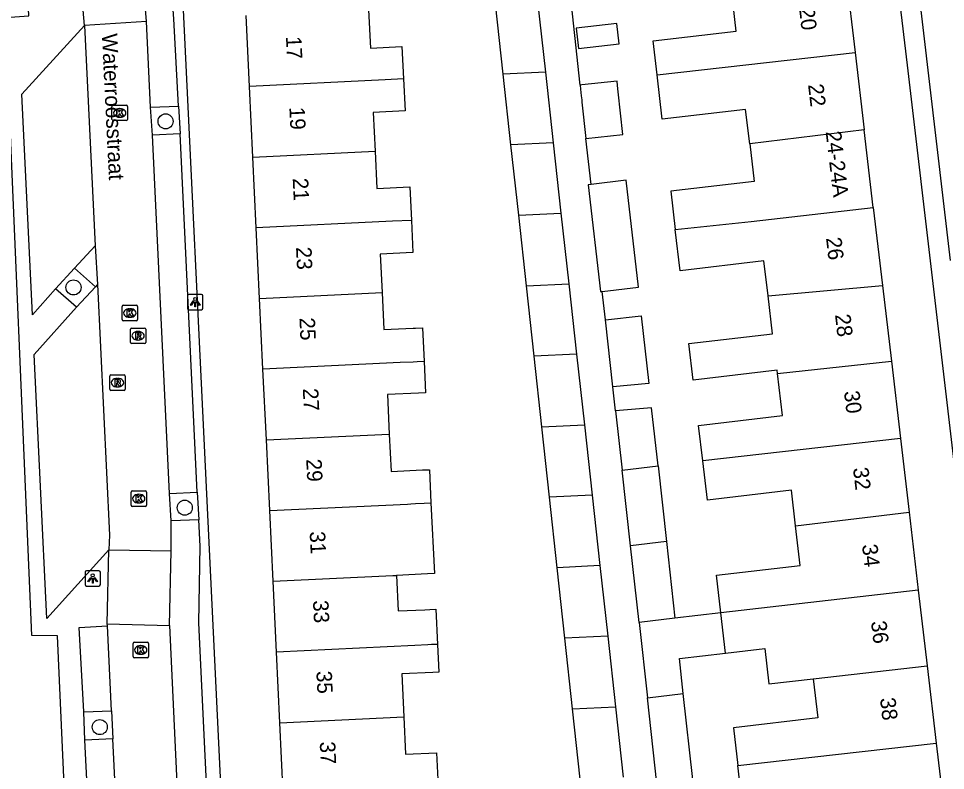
# Model space of a CAD drawing. Extents: x 162250 to 162654, y 380744 to 381605.
# Drawn here: x 162393.2 to 162453.3, y 381013.5 to 381062.2 of the extents above; entities that cross this region are included whole.
import ezdxf

# ---------------------------------------------------------------- set-up
doc = ezdxf.new("R2010")
doc.units = 0
for name, color, linetype in [('IMGEO_Boom', 7, 'Continuous'), ('IMGEO_Kolk', 7, 'Continuous'), ('IMGEO_Lichtpunt', 7, 'Continuous'), ('IMGEO_Openbare_ruimte_label', 7, 'Continuous'), ('IMGEO_Pand', 7, 'Continuous'), ('IMGEO_Pand_nummerreeks', 7, 'Continuous'), ('IMGEO_Parkeervlak_open', 7, 'Continuous'), ('IMGEO_Rijbaan_lokaal_open', 7, 'Continuous'), ('IMGEO_Rioolput', 7, 'Continuous'), ('IMGEO_Voetpad_open', 7, 'Continuous')]:
    doc.layers.add(name, color=color, linetype=linetype)

msp = doc.modelspace()

# ---------------------------------------------------------------- linework, layer by layer
at = {"layer": 'IMGEO_Boom'}
for centre in [(162402.768, 381055.57), (162396.792, 381044.803), (162404.011, 381030.518), (162398.497, 381016.292)]:
    msp.add_circle(centre, 0.489, dxfattribs=at)
at = {"layer": 'IMGEO_Kolk'}
for p, q in [((162399.291, 381055.69), (162399.291, 381056.542)), ((162399.366, 381056.616), (162400.218, 381056.616)), ((162399.779, 381056.396), (162399.804, 381056.396)), ((162400.292, 381056.542), (162400.292, 381055.69)), ((162399.802, 381055.836), (162399.777, 381055.836)), ((162400.218, 381055.616), (162399.366, 381055.616)), ((162399.948, 381042.717), (162399.948, 381043.569)), ((162400.023, 381043.643), (162400.875, 381043.643)), ((162400.436, 381043.423), (162400.461, 381043.423)), ((162400.949, 381043.569), (162400.949, 381042.717)), ((162400.875, 381042.643), (162400.023, 381042.643)), ((162400.459, 381042.863), (162400.434, 381042.863)), ((162400.529, 381030.678), (162400.529, 381031.53)), ((162400.604, 381031.604), (162401.456, 381031.604)), ((162401.017, 381031.384), (162401.042, 381031.384)), ((162401.53, 381031.53), (162401.53, 381030.678)), ((162401.456, 381030.604), (162400.604, 381030.604)), ((162401.04, 381030.824), (162401.015, 381030.824)), ((162400.655, 381020.865), (162400.655, 381021.717)), ((162400.73, 381021.791), (162401.582, 381021.791)), ((162401.143, 381021.571), (162401.168, 381021.571)), ((162401.656, 381021.717), (162401.656, 381020.865)), ((162401.166, 381021.011), (162401.141, 381021.011)), ((162401.582, 381020.791), (162400.73, 381020.791))]:
    msp.add_line(p, q, dxfattribs=at)
for points in [[(162399.291, 381055.69), (162399.291, 381056.542)], [(162399.366, 381056.616), (162400.218, 381056.616)], [(162399.612, 381056.316), (162399.735, 381056.316), (162399.735, 381056.165), (162399.865, 381056.316), (162400.029, 381056.316), (162399.883, 381056.165), (162400.036, 381055.916), (162399.884, 381055.916), (162399.799, 381056.08), (162399.735, 381056.013), (162399.735, 381055.916), (162399.612, 381055.916), (162399.612, 381056.316)], [(162400.292, 381056.542), (162400.292, 381055.69)], [(162400.218, 381055.616), (162399.366, 381055.616)], [(162399.948, 381042.717), (162399.948, 381043.569)], [(162400.023, 381043.643), (162400.875, 381043.643)], [(162400.269, 381043.343), (162400.392, 381043.343), (162400.392, 381043.192), (162400.522, 381043.343), (162400.686, 381043.343), (162400.54, 381043.192), (162400.693, 381042.943), (162400.541, 381042.943), (162400.456, 381043.107), (162400.392, 381043.04), (162400.392, 381042.943), (162400.269, 381042.943), (162400.269, 381043.343)], [(162400.949, 381043.569), (162400.949, 381042.717)], [(162400.875, 381042.643), (162400.023, 381042.643)], [(162400.529, 381030.678), (162400.529, 381031.53)], [(162400.604, 381031.604), (162401.456, 381031.604)], [(162400.85, 381031.304), (162400.973, 381031.304), (162400.973, 381031.153), (162401.103, 381031.304), (162401.267, 381031.304), (162401.121, 381031.153), (162401.274, 381030.904), (162401.122, 381030.904), (162401.037, 381031.068), (162400.973, 381031.001), (162400.973, 381030.904), (162400.85, 381030.904), (162400.85, 381031.304)], [(162401.53, 381031.53), (162401.53, 381030.678)], [(162401.456, 381030.604), (162400.604, 381030.604)], [(162400.655, 381020.865), (162400.655, 381021.717)], [(162400.73, 381021.791), (162401.582, 381021.791)], [(162400.976, 381021.491), (162401.099, 381021.491), (162401.099, 381021.34), (162401.229, 381021.491), (162401.393, 381021.491), (162401.247, 381021.34), (162401.4, 381021.091), (162401.248, 381021.091), (162401.163, 381021.255), (162401.099, 381021.188), (162401.099, 381021.091), (162400.976, 381021.091), (162400.976, 381021.491)], [(162401.656, 381021.717), (162401.656, 381020.865)], [(162401.582, 381020.791), (162400.73, 381020.791)]]:
    msp.add_lwpolyline(points, dxfattribs=at)
for centre, start, end in [((162399.368, 381056.54), 91.55205, 178.44795), ((162399.368, 381056.54), 91.55205, 178.44795), ((162400.216, 381056.54), 1.55205, 88.44795), ((162400.216, 381056.54), 1.55205, 88.44795), ((162399.368, 381055.692), 181.55205, 268.44795), ((162399.368, 381055.692), 181.55205, 268.44795), ((162400.216, 381055.692), 271.55205, 358.44795), ((162400.216, 381055.692), 271.55205, 358.44795), ((162400.025, 381043.567), 91.55205, 178.44795), ((162400.025, 381043.567), 91.55205, 178.44795), ((162400.873, 381043.567), 1.55205, 88.44795), ((162400.873, 381043.567), 1.55205, 88.44795), ((162400.025, 381042.719), 181.55205, 268.44795), ((162400.025, 381042.719), 181.55205, 268.44795), ((162400.873, 381042.719), 271.55205, 358.44795), ((162400.873, 381042.719), 271.55205, 358.44795), ((162400.606, 381031.528), 91.55205, 178.44795), ((162400.606, 381031.528), 91.55205, 178.44795), ((162401.454, 381031.528), 1.55205, 88.44795), ((162401.454, 381031.528), 1.55205, 88.44795), ((162400.606, 381030.68), 181.55205, 268.44795), ((162400.606, 381030.68), 181.55205, 268.44795), ((162401.454, 381030.68), 271.55205, 358.44795), ((162401.454, 381030.68), 271.55205, 358.44795), ((162400.732, 381021.715), 91.55205, 178.44795), ((162400.732, 381021.715), 91.55205, 178.44795), ((162401.58, 381021.715), 1.55205, 88.44795), ((162401.58, 381021.715), 1.55205, 88.44795), ((162400.732, 381020.867), 181.55205, 268.44795), ((162400.732, 381020.867), 181.55205, 268.44795), ((162401.58, 381020.867), 271.55205, 358.44795), ((162401.58, 381020.867), 271.55205, 358.44795)]:
    msp.add_arc(centre, 0.0765, start, end, dxfattribs=at)
for centre, major_axis, ratio, start_param, end_param in [((162399.778, 381056.116), (-0.387, 0.002), 0.722429, 4.712389, 7.853982), ((162399.803, 381056.116), (-0.39, 0.002), 0.717154, 1.570796, 4.712389), ((162400.435, 381043.143), (-0.387, 0.002), 0.722429, 4.712389, 7.853982), ((162400.46, 381043.143), (-0.39, 0.002), 0.717154, 1.570796, 4.712389), ((162401.016, 381031.104), (-0.387, 0.002), 0.722429, 4.712389, 7.853982), ((162401.041, 381031.104), (-0.39, 0.002), 0.717154, 1.570796, 4.712389), ((162401.142, 381021.291), (-0.387, 0.002), 0.722429, 4.712389, 7.853982), ((162401.167, 381021.291), (-0.39, 0.002), 0.717154, 1.570796, 4.712389)]:
    msp.add_ellipse(centre, major_axis=major_axis, ratio=ratio, start_param=start_param, end_param=end_param, dxfattribs=at)
at = {"layer": 'IMGEO_Lichtpunt'}
for p, q in [((162405.093, 381044.353), (162404.285, 381044.353)), ((162405.093, 381044.353), (162404.285, 381044.353)), ((162404.191, 381044.258), (162404.191, 381043.451)), ((162404.191, 381044.258), (162404.191, 381043.451)), ((162405.187, 381043.451), (162405.187, 381044.258)), ((162405.187, 381043.451), (162405.187, 381044.258)), ((162404.285, 381043.357), (162405.093, 381043.357)), ((162404.285, 381043.357), (162405.093, 381043.357)), ((162397.542, 381026.337), (162397.542, 381025.53)), ((162397.542, 381026.337), (162397.542, 381025.53)), ((162398.444, 381026.432), (162397.636, 381026.432)), ((162398.444, 381026.432), (162397.636, 381026.432)), ((162398.538, 381025.53), (162398.538, 381026.337)), ((162398.538, 381025.53), (162398.538, 381026.337)), ((162397.636, 381025.436), (162398.444, 381025.436)), ((162397.636, 381025.436), (162398.444, 381025.436))]:
    msp.add_line(p, q, dxfattribs=at)
for points in [[(162404.565, 381043.922), (162404.604, 381043.894), (162404.416, 381043.632), (162404.378, 381043.659), (162404.565, 381043.922)], [(162404.667, 381043.874), (162404.714, 381043.874), (162404.714, 381043.552), (162404.667, 381043.552), (162404.667, 381043.874)], [(162404.777, 381043.894), (162404.815, 381043.921), (162405.002, 381043.659), (162404.963, 381043.631), (162404.777, 381043.894)], [(162397.916, 381026.001), (162397.955, 381025.973), (162397.767, 381025.711), (162397.729, 381025.738), (162397.916, 381026.001)], [(162398.018, 381025.953), (162398.065, 381025.953), (162398.065, 381025.631), (162398.018, 381025.631), (162398.018, 381025.953)], [(162398.128, 381025.973), (162398.166, 381026), (162398.353, 381025.738), (162398.314, 381025.71), (162398.128, 381025.973)]]:
    msp.add_lwpolyline(points, dxfattribs=at)
for centre in [(162404.69, 381044.056), (162398.041, 381026.135)]:
    msp.add_circle(centre, 0.0994, dxfattribs=at)
for centre, start, end in [((162404.285, 381044.258), 90, 180), ((162404.285, 381044.258), 90, 180), ((162405.093, 381044.258), 0, 90), ((162405.093, 381044.258), 0, 90), ((162404.285, 381043.451), 180, 270), ((162404.285, 381043.451), 180, 270), ((162405.093, 381043.451), 270, 0), ((162405.093, 381043.451), 270, 360), ((162397.636, 381026.337), 90, 180), ((162397.636, 381026.337), 90, 180), ((162398.444, 381026.337), 0, 90), ((162398.444, 381026.337), 0, 90), ((162397.636, 381025.53), 180, 270), ((162397.636, 381025.53), 180, 270), ((162398.444, 381025.53), 270, 0), ((162398.444, 381025.53), 270, 360)]:
    msp.add_arc(centre, 0.0946, start, end, dxfattribs=at)
at = {"layer": 'IMGEO_Pand'}
for points in [[(162446.912, 381064.945), (162447.489, 381060.029)], [(162434.643, 381058.596), (162434.385, 381060.793), (162439.781, 381061.426), (162439.467, 381064.106)], [(162424.668, 381058.631), (162424.169, 381063.202)], [(162426.89, 381063.333), (162427.396, 381058.762)], [(162408.203, 381057.84), (162407.983, 381062.426)], [(162415.928, 381062.807), (162416.047, 381060.317), (162418.096, 381060.416), (162418.197, 381058.32)], [(162429.386, 381061.614), (162429.541, 381060.292), (162432.187, 381060.603), (162432.032, 381061.925), (162429.386, 381061.614)], [(162434.643, 381058.596), (162447.489, 381060.029)], [(162447.489, 381060.029), (162448.075, 381055.028)], [(162427.396, 381058.762), (162424.668, 381058.631)], [(162427.396, 381058.762), (162427.902, 381054.188)], [(162418.197, 381058.32), (162417.013, 381058.263), (162408.203, 381057.84)], [(162418.197, 381058.32), (162418.296, 381056.251), (162416.234, 381056.152), (162416.355, 381053.635)], [(162425.167, 381054.057), (162424.668, 381058.631)], [(162430.022, 381054.466), (162432.42, 381054.723), (162432.123, 381057.489), (162432.078, 381057.906), (162432.049, 381058.183), (162429.757, 381057.936), (162429.65, 381057.925)], [(162440.649, 381054.117), (162440.387, 381056.347), (162434.982, 381055.713), (162434.643, 381058.596)], [(162408.423, 381053.255), (162408.203, 381057.84)], [(162429.65, 381057.925), (162429.68, 381057.648), (162429.725, 381057.231), (162429.752, 381056.977), (162429.771, 381056.807), (162430.022, 381054.466)], [(162448.075, 381055.028), (162440.649, 381054.117)], [(162448.666, 381049.988), (162448.075, 381055.028)], [(162427.902, 381054.188), (162425.167, 381054.057)], [(162425.666, 381049.485), (162425.167, 381054.057)], [(162427.902, 381054.188), (162428.408, 381049.616)], [(162440.649, 381054.117), (162440.937, 381051.667), (162435.532, 381051.033), (162435.822, 381048.565)], [(162408.423, 381053.255), (162416.355, 381053.635)], [(162416.355, 381053.635), (162416.471, 381051.211), (162418.604, 381051.314), (162418.708, 381049.151)], [(162408.643, 381048.669), (162408.423, 381053.255)], [(162430.361, 381051.486), (162430.172, 381051.464), (162430.974, 381044.529), (162431.089, 381044.542)], [(162431.089, 381044.542), (162433.445, 381044.814), (162432.643, 381051.75), (162430.361, 381051.486)], [(162435.822, 381048.565), (162440.74, 381049.079), (162448.666, 381049.988)], [(162448.666, 381049.988), (162449.259, 381044.932)], [(162418.708, 381049.151), (162417.493, 381049.093), (162408.643, 381048.669)], [(162418.708, 381049.151), (162418.808, 381047.064), (162416.69, 381046.962), (162416.81, 381044.465)], [(162425.666, 381049.485), (162428.408, 381049.616)], [(162426.164, 381044.913), (162425.666, 381049.485)], [(162428.408, 381049.616), (162428.913, 381045.045)], [(162408.862, 381044.084), (162408.643, 381048.669)], [(162441.84, 381044.253), (162441.573, 381046.525), (162436.136, 381045.887), (162435.822, 381048.565)], [(162426.164, 381044.913), (162428.913, 381045.045)], [(162426.663, 381040.34), (162426.164, 381044.913)], [(162428.913, 381045.045), (162429.419, 381040.472)], [(162441.84, 381044.253), (162449.259, 381044.932)], [(162449.259, 381044.932), (162449.836, 381040.015)], [(162408.862, 381044.084), (162416.81, 381044.465)], [(162416.81, 381044.465), (162416.925, 381042.064), (162418.825, 381042.155), (162418.976, 381042.162), (162419.432, 381042.184), (162419.537, 381039.999)], [(162409.082, 381039.498), (162408.862, 381044.084)], [(162442.45, 381039.214), (162442.425, 381039.428), (162436.975, 381038.788), (162436.696, 381041.161), (162442.128, 381041.799), (162441.84, 381044.253)], [(162431.293, 381042.709), (162433.621, 381042.967), (162434.109, 381038.564), (162431.777, 381038.35)], [(162431.777, 381038.35), (162431.293, 381042.709)], [(162429.419, 381040.472), (162426.663, 381040.34)], [(162427.162, 381035.768), (162426.663, 381040.34)], [(162429.419, 381040.472), (162429.925, 381035.901)], [(162419.537, 381039.999), (162419.081, 381039.977), (162418.825, 381039.965), (162417.973, 381039.924), (162409.082, 381039.498)], [(162409.302, 381034.913), (162409.082, 381039.498)], [(162419.537, 381039.999), (162419.634, 381037.976), (162419.178, 381037.954), (162417.154, 381037.856), (162417.277, 381035.295)], [(162442.45, 381039.214), (162449.836, 381040.015)], [(162449.836, 381040.015), (162450.423, 381035.011)], [(162437.605, 381033.554), (162437.335, 381035.853), (162442.769, 381036.491), (162442.45, 381039.214)], [(162434.702, 381033.224), (162434.282, 381037.001), (162431.951, 381036.788)], [(162431.951, 381036.788), (162432.376, 381032.96)], [(162427.162, 381035.768), (162429.925, 381035.901)], [(162429.925, 381035.901), (162430.431, 381031.329)], [(162409.302, 381034.913), (162417.277, 381035.295)], [(162417.277, 381035.295), (162417.393, 381032.864), (162419.432, 381032.962), (162419.875, 381032.983), (162419.979, 381030.828)], [(162427.661, 381031.196), (162427.162, 381035.768)], [(162409.522, 381030.327), (162409.302, 381034.913)], [(162450.423, 381035.011), (162437.605, 381033.554)], [(162450.423, 381035.011), (162450.985, 381030.219)], [(162443.63, 381029.333), (162443.358, 381031.645), (162437.904, 381031.005), (162437.605, 381033.554)], [(162432.376, 381032.96), (162434.702, 381033.224)], [(162432.922, 381028.042), (162432.376, 381032.96)], [(162434.702, 381033.224), (162435.246, 381028.322)], [(162430.431, 381031.329), (162427.661, 381031.196)], [(162428.159, 381026.626), (162427.661, 381031.196)], [(162430.431, 381031.329), (162430.936, 381026.759)], [(162409.522, 381030.327), (162418.453, 381030.755), (162418.68, 381030.766), (162418.977, 381030.78), (162419.535, 381030.807), (162419.979, 381030.828)], [(162419.979, 381030.828), (162420.199, 381026.244), (162419.756, 381026.222), (162417.746, 381026.126)], [(162409.742, 381025.742), (162409.522, 381030.327)], [(162443.63, 381029.333), (162450.985, 381030.219)], [(162450.985, 381030.219), (162451.578, 381025.162)], [(162438.785, 381023.689), (162438.498, 381026.14), (162443.93, 381026.778), (162443.63, 381029.333)], [(162435.246, 381028.322), (162432.922, 381028.042)], [(162433.473, 381023.078), (162432.922, 381028.042)], [(162435.246, 381028.322), (162435.799, 381023.345)], [(162430.936, 381026.759), (162428.159, 381026.626)], [(162428.658, 381022.052), (162428.159, 381026.626)], [(162430.936, 381026.759), (162431.442, 381022.186)], [(162409.742, 381025.742), (162417.499, 381026.114), (162417.746, 381026.126)], [(162409.962, 381021.156), (162409.742, 381025.742)], [(162417.746, 381026.126), (162417.857, 381023.82), (162419.573, 381023.902), (162419.896, 381023.918), (162420.293, 381023.937), (162420.403, 381021.656)], [(162451.578, 381025.162), (162438.785, 381023.689)], [(162451.578, 381025.162), (162452.153, 381020.264)], [(162435.799, 381023.345), (162433.473, 381023.078)], [(162438.785, 381023.689), (162435.799, 381023.345)], [(162439.09, 381021.093), (162438.785, 381023.689)], [(162433.473, 381023.078), (162434.015, 381018.195)], [(162431.442, 381022.186), (162428.658, 381022.052)], [(162429.157, 381017.479), (162428.658, 381022.052)], [(162431.442, 381022.186), (162431.948, 381017.613)], [(162420.403, 381021.656), (162420.006, 381021.637), (162419.785, 381021.626), (162418.933, 381021.586), (162409.962, 381021.156)], [(162420.403, 381021.656), (162420.49, 381019.85), (162420.093, 381019.831), (162418.086, 381019.735), (162418.219, 381016.955)], [(162410.182, 381016.57), (162409.962, 381021.156)], [(162436.341, 381018.46), (162436.088, 381020.741), (162439.09, 381021.093)], [(162439.09, 381021.093), (162441.622, 381021.39), (162441.884, 381019.093), (162444.772, 381019.422)], [(162444.772, 381019.422), (162452.153, 381020.264)], [(162452.153, 381020.264), (162452.741, 381015.249)], [(162444.772, 381019.422), (162445.07, 381016.882), (162439.597, 381016.239), (162439.884, 381013.794)], [(162434.015, 381018.195), (162436.341, 381018.46)], [(162434.632, 381012.632), (162436.959, 381012.89), (162436.341, 381018.46)], [(162434.632, 381012.632), (162434.015, 381018.195)], [(162429.157, 381017.479), (162431.948, 381017.613)], [(162429.655, 381012.908), (162429.157, 381017.479)], [(162431.948, 381017.613), (162432.453, 381013.042)], [(162410.182, 381016.57), (162418.219, 381016.955)], [(162418.219, 381016.955), (162418.336, 381014.524), (162420.345, 381014.621), (162420.449, 381012.467)], [(162410.401, 381011.985), (162410.182, 381016.57)], [(162439.884, 381013.794), (162452.741, 381015.249)], [(162452.741, 381015.249), (162453.317, 381010.345)], [(162445.922, 381009.442), (162442.621, 381009.039), (162442.341, 381011.426), (162440.191, 381011.174), (162439.884, 381013.794)]]:
    msp.add_lwpolyline(points, dxfattribs=at)
at = {"layer": 'IMGEO_Parkeervlak_open'}
for points in [[(162401.788, 381056.497), (162403.601, 381056.563)], [(162403.702, 381054.752), (162401.91, 381054.668)], [(162395.636, 381044.716), (162396.858, 381046.041)], [(162398.219, 381044.849), (162396.998, 381043.512)], [(162403.024, 381031.439), (162404.812, 381031.518)], [(162404.923, 381029.732), (162403.119, 381029.661)], [(162397.466, 381017.272), (162399.249, 381017.345)], [(162399.335, 381015.527), (162397.528, 381015.45)]]:
    msp.add_lwpolyline(points, dxfattribs=at)
at = {"layer": 'IMGEO_Rijbaan_lokaal_open'}
for points in [[(162397.515, 381061.788), (162397.097, 381066.528)], [(162401.527, 381062.05), (162401.144, 381066.824)], [(162401.527, 381062.05), (162397.515, 381061.788)], [(162397.515, 381061.788), (162398.21, 381047.495)], [(162401.788, 381056.497), (162401.527, 381062.05)], [(162401.91, 381054.668), (162401.788, 381056.497)], [(162403.024, 381031.439), (162401.91, 381054.668)], [(162398.21, 381047.495), (162398.356, 381044.989)], [(162398.356, 381044.989), (162399.133, 381028.737), (162399.081, 381027.795)], [(162403.119, 381029.661), (162403.024, 381031.439)], [(162403.125, 381027.725), (162403.119, 381029.661)], [(162398.971, 381022.978), (162399.081, 381027.795)], [(162399.081, 381027.795), (162403.125, 381027.725)], [(162403.025, 381022.884), (162403.125, 381027.725)], [(162398.996, 381022.855), (162398.971, 381022.978)], [(162398.971, 381022.978), (162403.025, 381022.884)], [(162399.249, 381017.345), (162398.996, 381022.855)], [(162403.025, 381022.884), (162403.827, 381005.703)], [(162399.249, 381017.345), (162399.335, 381015.527)], [(162400.183, 380998.483), (162399.335, 381015.527)]]:
    msp.add_lwpolyline(points, dxfattribs=at)
at = {"layer": 'IMGEO_Rioolput'}
for p, q in [((162400.481, 381041.238), (162400.481, 381042.09)), ((162400.556, 381042.164), (162401.408, 381042.164)), ((162400.969, 381041.944), (162400.994, 381041.944)), ((162401.482, 381042.09), (162401.482, 381041.238)), ((162400.992, 381041.384), (162400.967, 381041.384)), ((162401.408, 381041.164), (162400.556, 381041.164)), ((162399.147, 381038.198), (162399.147, 381039.05)), ((162399.222, 381039.124), (162400.074, 381039.124)), ((162399.635, 381038.904), (162399.66, 381038.904)), ((162400.148, 381039.05), (162400.148, 381038.198)), ((162399.658, 381038.344), (162399.633, 381038.344)), ((162400.074, 381038.124), (162399.222, 381038.124))]:
    msp.add_line(p, q, dxfattribs=at)
for points in [[(162400.481, 381041.238), (162400.481, 381042.09)], [(162400.556, 381042.164), (162401.408, 381042.164)], [(162401.07, 381041.862), (162400.818, 381041.864), (162400.818, 381041.464)], [(162401.482, 381042.09), (162401.482, 381041.238)], [(162400.818, 381041.464), (162400.942, 381041.464), (162400.942, 381041.626), (162400.953, 381041.626)], [(162400.996, 381041.783), (162400.942, 381041.783), (162400.942, 381041.702)], [(162400.942, 381041.702), (162400.994, 381041.702)], [(162401, 381041.597), (162401.071, 381041.464), (162401.211, 381041.464), (162401.146, 381041.59)], [(162401.408, 381041.164), (162400.556, 381041.164)], [(162399.147, 381038.198), (162399.147, 381039.05)], [(162399.222, 381039.124), (162400.074, 381039.124)], [(162400.148, 381039.05), (162400.148, 381038.198)], [(162399.736, 381038.822), (162399.484, 381038.824), (162399.484, 381038.424)], [(162399.484, 381038.424), (162399.608, 381038.424), (162399.608, 381038.586), (162399.619, 381038.586)], [(162399.662, 381038.743), (162399.608, 381038.743), (162399.608, 381038.662)], [(162399.608, 381038.662), (162399.66, 381038.662)], [(162399.666, 381038.557), (162399.737, 381038.424), (162399.877, 381038.424), (162399.812, 381038.55)], [(162400.074, 381038.124), (162399.222, 381038.124)]]:
    msp.add_lwpolyline(points, dxfattribs=at)
for centre, radius, start, end in [((162400.558, 381042.088), 0.0765, 91.55205, 178.44795), ((162400.558, 381042.088), 0.0765, 91.55205, 178.44795), ((162401.069, 381041.752), 0.109, 350.36119, 89.41601), ((162401.406, 381042.088), 0.0765, 1.55205, 88.44795), ((162401.406, 381042.088), 0.0765, 1.55205, 88.44795), ((162400.952, 381041.573), 0.0533, 26.02933, 88.69889), ((162400.978, 381041.891), 0.19, 274.7715, 282.96867), ((162401.002, 381041.687), 0.0964, 77.00612, 93.18647), ((162401.016, 381041.744), 0.0378, 276.66336, 79.67722), ((162401.067, 381041.752), 0.112, 277.58423, 350.98172), ((162401.051, 381041.537), 0.108, 29.51342, 73.79051), ((162400.558, 381041.24), 0.0765, 181.55205, 268.44795), ((162400.558, 381041.24), 0.0765, 181.55205, 268.44795), ((162401.406, 381041.24), 0.0765, 271.55205, 358.44795), ((162401.406, 381041.24), 0.0765, 271.55205, 358.44795), ((162399.224, 381039.048), 0.0765, 91.55205, 178.44795), ((162399.224, 381039.048), 0.0765, 91.55205, 178.44795), ((162400.072, 381039.048), 0.0765, 1.55205, 88.44795), ((162400.072, 381039.048), 0.0765, 1.55205, 88.44795), ((162399.618, 381038.533), 0.0533, 26.02933, 88.69889), ((162399.644, 381038.851), 0.19, 274.7715, 282.96867), ((162399.668, 381038.647), 0.0964, 77.00612, 93.18647), ((162399.682, 381038.704), 0.0378, 276.66336, 79.67722), ((162399.735, 381038.712), 0.109, 350.36119, 89.41601), ((162399.733, 381038.712), 0.112, 277.58423, 350.98172), ((162399.717, 381038.497), 0.108, 29.51342, 73.79051), ((162399.224, 381038.2), 0.0765, 181.55205, 268.44795), ((162399.224, 381038.2), 0.0765, 181.55205, 268.44795), ((162400.072, 381038.2), 0.0765, 271.55205, 358.44795), ((162400.072, 381038.2), 0.0765, 271.55205, 358.44795)]:
    msp.add_arc(centre, radius, start, end, dxfattribs=at)
for centre, major_axis, ratio, start_param, end_param in [((162400.968, 381041.664), (-0.387, 0.002), 0.722429, 4.712389, 7.853982), ((162400.993, 381041.664), (-0.39, 0.002), 0.717154, 1.570796, 4.712389), ((162399.634, 381038.624), (-0.387, 0.002), 0.722429, 4.712389, 7.853982), ((162399.659, 381038.624), (-0.39, 0.002), 0.717154, 1.570796, 4.712389)]:
    msp.add_ellipse(centre, major_axis=major_axis, ratio=ratio, start_param=start_param, end_param=end_param, dxfattribs=at)
at = {"layer": 'IMGEO_Voetpad_open'}
for points in [[(162460.106, 380980.583), (162457.834, 381000), (162450.879, 381059.205), (162445.423, 381105.014)], [(162429.65, 381057.925), (162426.098, 381090.941), (162424.979, 381101.344), (162434.792, 381103.761)], [(162397.638, 380979.87), (162396.746, 381000), (162395.762, 381022.213), (162394.094, 381022.237), (162392.384, 381062.316), (162393.904, 381062.404), (162392.344, 381095.083)], [(162402.365, 381094.66), (162406.928, 381000), (162407.912, 380979.576)], [(162403.601, 381056.563), (162403.31, 381062.212), (162402.812, 381069.054), (162402.317, 381079.743)], [(162453.668, 381046.538), (162450.994, 381069.409)], [(162395.636, 381044.716), (162394.138, 381043.031), (162393.433, 381057.342), (162397.515, 381061.788)], [(162403.601, 381056.563), (162403.702, 381054.752)], [(162404.812, 381031.518), (162403.702, 381054.752)], [(162430.361, 381051.486), (162430.022, 381054.466)], [(162396.858, 381046.041), (162398.21, 381047.495)], [(162396.858, 381046.041), (162398.219, 381044.849)], [(162398.356, 381044.989), (162398.219, 381044.849)], [(162396.998, 381043.512), (162395.636, 381044.716)], [(162431.293, 381042.709), (162431.089, 381044.542)], [(162399.081, 381027.795), (162395.066, 381023.329), (162394.25, 381040.459), (162396.998, 381043.512)], [(162431.951, 381036.788), (162431.777, 381038.35)], [(162404.812, 381031.518), (162404.923, 381029.732)], [(162405.739, 381005.822), (162404.924, 381023.052), (162405.007, 381028.026), (162404.923, 381029.732)], [(162397.466, 381017.272), (162397.169, 381022.757), (162398.996, 381022.855)], [(162397.528, 381015.45), (162397.466, 381017.272)], [(162398.395, 380998.385), (162397.528, 381015.45)]]:
    msp.add_lwpolyline(points, dxfattribs=at)

# ---------------------------------------------------------------- texts
at = {"layer": 'IMGEO_Openbare_ruimte_label'}
msp.add_text('Waterroosstraat', height=1, rotation=272.80805, dxfattribs=at).set_placement((162398.633, 381061.245))
at = {"layer": 'IMGEO_Pand_nummerreeks'}
for s, rotation, p in [('20', 276.69027, (162443.848, 381062.906)), ('17', 272.74459, (162410.571, 381061.067)), ('22', 276.69027, (162444.43, 381057.951)), ('19', 272.74459, (162410.791, 381056.484)), ('24-24A', 276.68621, (162445.574, 381054.895)), ('21', 272.74459, (162411.011, 381051.88)), ('26', 276.68991, (162445.596, 381048.005)), ('23', 272.74459, (162411.226, 381047.411)), ('25', 272.74426, (162411.446, 381042.828)), ('28', 276.68991, (162446.18, 381043.027)), ('27', 272.74426, (162411.665, 381038.245)), ('30', 276.68991, (162446.763, 381038.052)), ('29', 272.74426, (162411.885, 381033.663)), ('32', 276.68991, (162447.347, 381033.083)), ('31', 272.74426, (162412.11, 381028.968)), ('34', 276.68991, (162447.93, 381028.105)), ('33', 272.74426, (162412.324, 381024.499)), ('36', 276.68991, (162448.514, 381023.13)), ('35', 272.74426, (162412.544, 381019.916)), ('38', 276.68991, (162449.097, 381018.152)), ('37', 272.74459, (162412.764, 381015.335))]:
    msp.add_text(s, height=1, rotation=rotation, dxfattribs=at).set_placement(p)

doc.saveas('drawing.dxf')
